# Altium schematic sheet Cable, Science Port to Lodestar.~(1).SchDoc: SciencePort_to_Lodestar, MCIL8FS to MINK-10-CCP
size B; Organization: Monterey Bay Aquarium Research Institute; Address1: 7700 Sandholdt Rd; Address2: Moss Landing, CA 95039-9644; CompanyName: MBARI; DrawnBy: Hans Thomas; Engineer: Hans Thomas
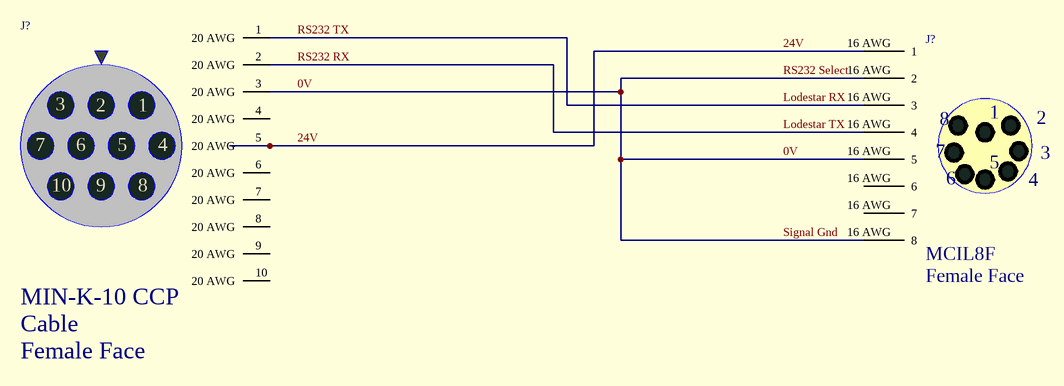
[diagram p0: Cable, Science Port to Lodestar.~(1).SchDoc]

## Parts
(Parts that share a designator on the sheet are numbered #1, #2 ... from top to bottom, then left to right.)
J?#1  MIN-K-10 CCP  DescSheet: Cable  View: Female Face
J?#2  MCIL8F  View: Female Face

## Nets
0V: J?#1.3(20_AWG) J?#2.16_AWG(2)  [also labelled RS232 Select, Signal Gnd]
24V: J?#1.5(20_AWG) J?#2.16_AWG(1)
Lodestar RX: J?#1.1(20_AWG) J?#2.16_AWG(3)  [also labelled RS232 TX]
Lodestar TX: J?#1.2(20_AWG) J?#2.16_AWG(4)  [also labelled RS232 RX]

Not connected (* = marked no-connect by the designer): J?#1 4(20_AWG) 6(20_AWG) 7(20_AWG) 8(20_AWG) 9(20_AWG) 10(20_AWG)

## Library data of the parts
J?#1 = SEACON-MINM-10-CCP-SOC: Seacon MINM-10/L-CCP Connector
J?#2 = SUBCONN-MCxx8F: Subconn MCIL8F Connector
